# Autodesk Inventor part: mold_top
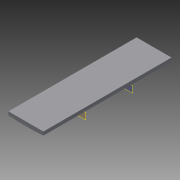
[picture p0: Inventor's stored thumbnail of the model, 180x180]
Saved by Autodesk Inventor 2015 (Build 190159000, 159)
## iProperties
Created: 2015-04
Part Number: mold_top
Material: Generic
Document SubType Name: Modeling
Designer: sungeun
Density: 1 g/cm^3
Appearance: Default
Author: sungeun
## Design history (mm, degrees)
sketch "Sketch1"
  geometry: L1 (150, 550)-(-150, 550); L2 (-150, 550)-(-150, -550); L3 (-150, -550)-(150, -550); L4 (150, -550)-(150, 550); L5 (150, 550)-(-150, -550); L6 (-150, 550)-(150, -550); 1 further point
  constraints: 12 end point, 2 midpoint, 2 parallel, 1 horizontal, 1 perpendicular
  dimensions: "d0" = 300 distance of L3.end L2.end; "d1" = 1100 distance of L2.end L1.end
extrude "Extrusion1" new body sketch "Sketch1" distance "d2" = 50; taper "d3" = 0 deg
sketch "Sketch2"
  geometry: L1 (300, -50)-(0, -50); L2 (300, -50)-(0, -50) reference; A1 r 2000 centre (150, -2044.367) between (300, -50) and (0, -50); 1 further point
  constraints: 2 end point, 2 point on circle, 1 centre point, 1 collinear
  dimensions: "d17" = 2000 radius of A1
sketch "Sketch3"
  geometry: L1 (0, 50)-(300, 50); L2 (300, 50)-(0, 50) reference; A1 r 2000 centre (150, 2044.367) between (0, 50) and (300, 50); 1 further point
  constraints: 2 end point, 2 point on circle, 1 centre point, 1 collinear
  dimensions: "d5" = 2000 radius of A1
workplane "Work Plane1"
workplane "Work Plane2"
sketch "Sketch5"
  geometry: L1 (0, 50)-(300, 50); L2 (300, 0)-(300, 50) reference; A1 r 900 centre (150, 937.412) between (0, 50) and (300, 50); 1 further point
  constraints: 2 end point, 2 point on circle, 1 centre point, 1 perpendicular
  dimensions: "d9" = 900 radius of A1
sketch "Sketch6"
  geometry: L1 (0, -50)-(300, -50); A1 r 1400 centre (150, -1441.941) between (300, -50) and (0, -50); 1 further point
  constraints: 2 end point, 2 point on circle, 1 centre point, 1 horizontal
  dimensions: "d10" = 1400 radius of A1
loft "Loft1" sketch "Sketch5", "Sketch6" dims "d11" = 0, "d12" = 90 deg, "d13" = 0, "d14" = 90 deg, "d15" = 0, "d16" = 90 deg, "d18" = 0, "d19" = 90 deg
sketch "Sketch7"
  geometry: L1 (150, -550)-(-150, -550); L2 (-150, -550)-(-150, 550); L3 (-150, 550)-(150, 550); L4 (150, 550)-(150, -550); 1 further point
  constraints: 8 end point, 2 parallel, 1 horizontal, 1 perpendicular
extrude "Extrusion2" new body sketch "Sketch7" distance "d20" = 80; taper "d21" = 0 deg
combine "Combine1"
  body "Solid1"
body "Solid2"
